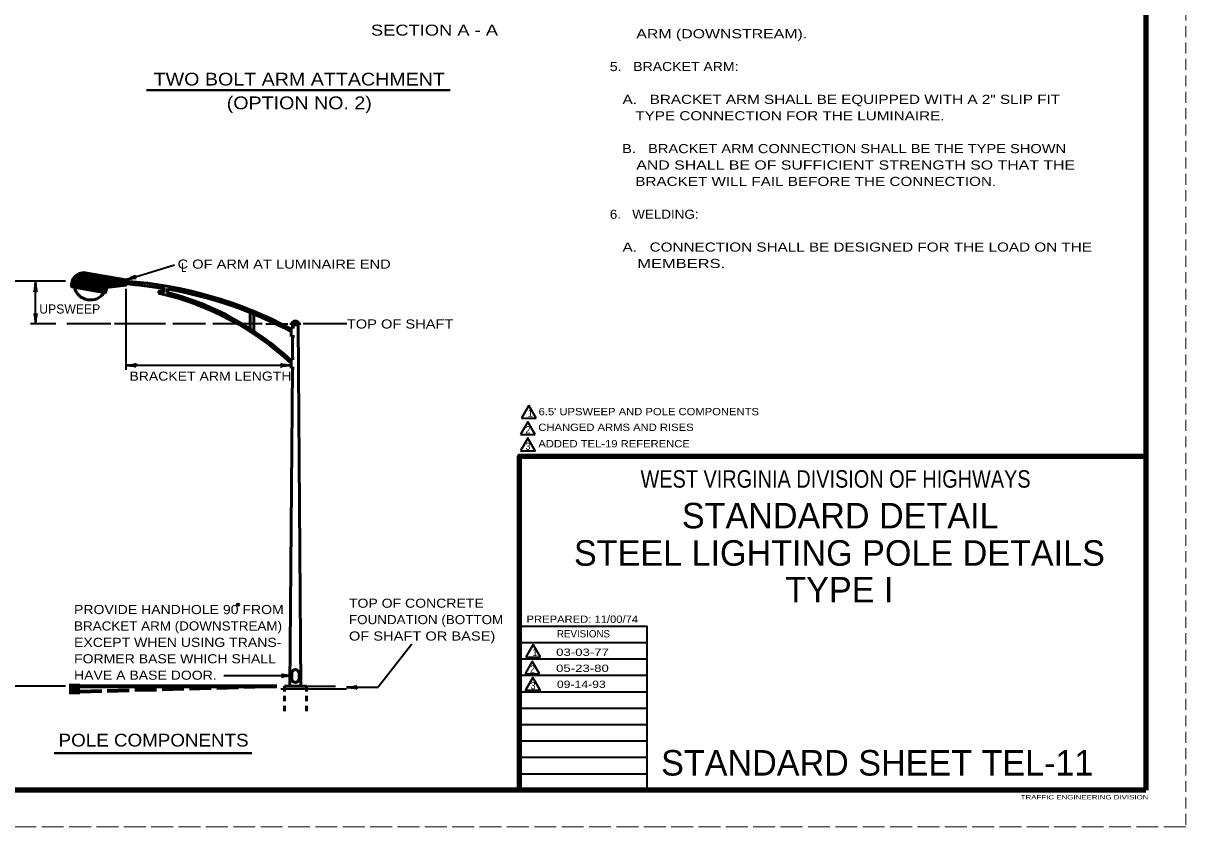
# Model space of a CAD drawing. Extents: x -1 to 679, y 1 to 441.
# Drawn here: x 360.8 to 679.4, y 0.8 to 221.2 of the extents above; entities that cross this region are included whole.
import ezdxf
from ezdxf.enums import TextEntityAlignment as Align

# ---------------------------------------------------------------- set-up
doc = ezdxf.new("R2010")
doc.units = 0
doc.header["$PDMODE"] = 32
doc.header["$PDSIZE"] = 0.5
for name, pattern in [('LONG_DASHED', [7.5, 6, -1.5]), ('MEDIUM_DASHED', [4.5, 3, -1.5]), ('SHORT_DASHED', [2.7, 1.5, -1.2])]:
    doc.linetypes.add(name, pattern=pattern)
doc.layers.add('1', color=7, linetype='Continuous', lineweight=13)
doc.layers.add('61', color=7, linetype='Continuous', lineweight=35)

msp = doc.modelspace()

# ---------------------------------------------------------------- linework, layer by layer
at = {"layer": '1', "linetype": 'MEDIUM_DASHED'}
msp.add_line((679.412, 440.866), (679.392, 0.846), dxfattribs=at)
at = {"layer": '1', "lineweight": 40}
for p, q in [((394.595, 202.791), (477.805, 202.791)), ((369.301, 21.01), (423.451, 21.01))]:
    msp.add_line(p, q, dxfattribs=at)
at = {"layer": '1', "lineweight": 35}
for p, q in [((388.908, 150.796), (402.224, 154.896)), ((372.357, 150.421), (353.908, 150.421)), ((364.189, 138.702), (364.189, 150.421)), ((388.908, 148.296), (388.908, 126.153)), ((369.783, 138.702), (362.783, 138.702)), ((384.783, 138.702), (372.783, 138.702)), ((399.783, 138.702), (385.783, 138.702)), ((410.783, 138.702), (401.783, 138.702)), ((426.283, 138.702), (412.783, 138.702)), ((427.283, 138.702), (433.283, 138.702)), ((449.533, 138.702), (437.533, 138.702)), ((434.213, 127.343), (388.908, 127.343)), ((499.351, 116.373), (497.351, 112.908)), ((501.351, 112.908), (499.351, 116.373)), ((499.081, 111.858), (497.081, 108.394)), ((497.351, 112.908), (501.351, 112.908)), ((501.081, 108.394), (499.081, 111.858)), ((497.081, 108.394), (501.081, 108.394)), ((531.792, 51.266), (496.812, 51.266)), ((467.308, 50.878), (458.129, 39.061)), ((500.599, 50.778), (498.599, 47.314)), ((502.599, 47.314), (500.599, 50.778)), ((531.792, 46.766), (496.812, 46.766)), ((500.329, 46.264), (498.329, 42.8)), ((498.599, 47.314), (502.599, 47.314)), ((502.329, 42.8), (500.329, 46.264)), ((434.485, 42.243), (415.78, 42.243)), ((531.792, 42.266), (496.812, 42.266)), ((498.329, 42.8), (502.329, 42.8)), ((372.357, 39.421), (353.908, 39.421)), ((431.408, 38.671), (449.408, 38.671)), ((438.408, 39.421), (446.408, 39.421)), ((449.404, 39.061), (458.129, 39.061)), ((531.792, 37.746), (496.812, 37.746)), ((531.792, 33.266), (496.812, 33.266)), ((531.792, 28.786), (496.812, 28.786)), ((531.792, 24.286), (496.812, 24.286)), ((531.792, 19.786), (496.812, 19.786)), ((531.792, 15.266), (496.812, 15.266))]:
    msp.add_line(p, q, dxfattribs=at)
at = {"layer": '1', "lineweight": 53}
for p, q in [((374.06, 149.277), (375.11, 150.327)), ((374.061, 149.384), (375.004, 150.327)), ((374.061, 149.172), (375.216, 150.327)), ((374.062, 149.492), (374.898, 150.327)), ((374.069, 149.604), (374.792, 150.327)), ((374.071, 149.075), (375.322, 150.327)), ((374.08, 148.978), (375.428, 150.327)), ((374.083, 149.724), (374.686, 150.327)), ((374.089, 148.882), (375.535, 150.327)), ((374.097, 149.844), (374.639, 150.387)), ((374.118, 149.971), (374.639, 150.493)), ((374.143, 148.83), (375.641, 150.327)), ((374.148, 150.108), (376.717, 152.676)), ((374.179, 150.245), (376.576, 152.642)), ((374.23, 150.402), (376.422, 152.593)), ((374.233, 148.814), (375.747, 150.327)), ((374.284, 150.562), (376.262, 152.54)), ((374.324, 148.798), (375.853, 150.327)), ((374.365, 150.748), (376.076, 152.459)), ((374.414, 148.782), (375.959, 150.327)), ((374.46, 150.949), (375.867, 152.357)), ((374.504, 148.766), (376.065, 150.327)), ((374.594, 148.75), (376.171, 150.327)), ((374.613, 151.209), (375.612, 152.208)), ((374.661, 150.515), (376.85, 152.703)), ((374.684, 148.735), (376.277, 150.327)), ((374.767, 150.515), (376.982, 152.73)), ((374.774, 148.719), (376.383, 150.327)), ((374.865, 148.703), (376.489, 150.327)), ((374.873, 150.515), (377.1, 152.741)), ((374.955, 148.687), (376.595, 150.327)), ((374.98, 150.515), (377.217, 152.752)), ((375.045, 148.671), (376.701, 150.327)), ((375.085, 151.787), (375.088, 151.79)), ((375.086, 150.515), (377.334, 152.763)), ((375.135, 148.655), (376.807, 150.327)), ((375.192, 150.515), (377.44, 152.763)), ((375.225, 148.639), (376.913, 150.327)), ((375.298, 150.515), (377.545, 152.762)), ((375.315, 148.623), (377.019, 150.327)), ((375.404, 150.515), (377.65, 152.761)), ((375.406, 148.607), (377.125, 150.327)), ((375.496, 148.591), (377.232, 150.327)), ((375.51, 150.515), (377.751, 152.756)), ((375.586, 148.576), (377.338, 150.327)), ((375.616, 150.515), (377.847, 152.746)), ((375.676, 148.56), (377.444, 150.327)), ((375.722, 150.515), (377.938, 152.73)), ((375.766, 148.544), (377.55, 150.327)), ((375.828, 150.515), (378.028, 152.714)), ((375.856, 148.528), (377.656, 150.327)), ((375.934, 150.515), (378.118, 152.699)), ((375.947, 148.512), (377.762, 150.327)), ((376.037, 148.496), (377.868, 150.327)), ((376.04, 150.515), (378.208, 152.683)), ((376.127, 148.48), (377.974, 150.327)), ((376.146, 150.515), (378.298, 152.667)), ((376.217, 148.464), (378.08, 150.327)), ((376.252, 150.515), (378.388, 152.651)), ((376.307, 148.448), (378.186, 150.327)), ((376.358, 150.515), (378.479, 152.635)), ((376.397, 148.433), (378.292, 150.327)), ((376.464, 150.515), (378.569, 152.619)), ((376.488, 148.417), (378.398, 150.327)), ((376.571, 150.515), (378.659, 152.603)), ((376.578, 148.401), (378.504, 150.327)), ((376.668, 148.385), (378.61, 150.327)), ((376.677, 150.515), (378.749, 152.587)), ((376.758, 148.369), (378.716, 150.327)), ((376.783, 150.515), (378.839, 152.571)), ((376.848, 148.353), (378.823, 150.327)), ((376.889, 150.515), (378.929, 152.555)), ((376.938, 148.337), (378.929, 150.327)), ((376.995, 150.515), (379.02, 152.54)), ((377.029, 148.321), (379.035, 150.327)), ((377.101, 150.515), (379.11, 152.524)), ((377.119, 148.305), (379.141, 150.327)), ((377.207, 150.515), (379.2, 152.508)), ((377.209, 148.289), (379.247, 150.327)), ((377.299, 148.273), (379.353, 150.327)), ((377.313, 150.515), (379.29, 152.492)), ((377.389, 148.258), (379.459, 150.327)), ((377.419, 150.515), (379.38, 152.476)), ((377.479, 148.242), (379.565, 150.327)), ((377.525, 150.515), (379.471, 152.46)), ((377.57, 148.226), (379.671, 150.327)), ((377.631, 150.515), (379.561, 152.444)), ((377.66, 148.21), (379.777, 150.327)), ((377.737, 150.515), (379.651, 152.428)), ((377.75, 148.194), (379.883, 150.327)), ((377.84, 148.178), (379.989, 150.327)), ((377.843, 150.515), (379.741, 152.412)), ((377.93, 148.162), (380.095, 150.327)), ((377.949, 150.515), (379.831, 152.397)), ((378.02, 148.146), (380.201, 150.327)), ((378.055, 150.515), (379.921, 152.381)), ((378.111, 148.13), (380.308, 150.327)), ((378.162, 150.515), (380.012, 152.365)), ((378.201, 148.114), (380.414, 150.327)), ((378.268, 150.515), (380.102, 152.349)), ((378.291, 148.099), (380.52, 150.327)), ((378.374, 150.515), (380.192, 152.333)), ((378.381, 148.083), (380.626, 150.327)), ((378.471, 148.067), (380.732, 150.327)), ((378.48, 150.515), (380.282, 152.317)), ((378.561, 148.051), (380.838, 150.327)), ((378.586, 150.515), (380.372, 152.301)), ((378.652, 148.035), (380.944, 150.327)), ((378.692, 150.515), (380.462, 152.285)), ((378.742, 148.019), (381.05, 150.327)), ((378.798, 150.515), (380.553, 152.269)), ((378.832, 148.003), (381.156, 150.327)), ((378.904, 150.515), (380.643, 152.253)), ((378.922, 147.987), (381.262, 150.327)), ((379.01, 150.515), (380.733, 152.237)), ((379.012, 147.971), (381.368, 150.327)), ((379.102, 147.955), (381.474, 150.327)), ((379.116, 150.515), (380.823, 152.222)), ((379.193, 147.94), (381.58, 150.327)), ((379.222, 150.515), (380.913, 152.206)), ((379.283, 147.924), (381.686, 150.327)), ((379.328, 150.515), (381.003, 152.19)), ((379.373, 147.908), (381.792, 150.327)), ((379.434, 150.515), (381.094, 152.174)), ((379.463, 147.892), (381.899, 150.327)), ((379.54, 150.515), (381.184, 152.158)), ((379.553, 147.876), (382.005, 150.327)), ((379.643, 147.86), (382.111, 150.327)), ((379.647, 150.515), (381.274, 152.142)), ((379.734, 147.844), (382.217, 150.327)), ((379.753, 150.515), (381.364, 152.126)), ((379.824, 147.828), (382.323, 150.327)), ((379.859, 150.515), (381.454, 152.11)), ((379.914, 147.812), (382.429, 150.327)), ((379.965, 150.515), (381.544, 152.094)), ((380.004, 147.796), (382.535, 150.327)), ((380.071, 150.515), (381.635, 152.078)), ((380.094, 147.781), (382.641, 150.327)), ((380.177, 150.515), (381.725, 152.063)), ((380.184, 147.765), (382.747, 150.327)), ((380.275, 147.749), (382.853, 150.327)), ((380.283, 150.515), (381.815, 152.047)), ((380.365, 147.733), (382.959, 150.327)), ((380.389, 150.515), (381.905, 152.031)), ((380.455, 147.717), (383.065, 150.327)), ((380.495, 150.515), (381.995, 152.015)), ((380.545, 147.701), (383.171, 150.327)), ((380.601, 150.515), (382.085, 151.999)), ((380.635, 147.685), (383.277, 150.327)), ((380.707, 150.515), (382.175, 151.983)), ((380.725, 147.669), (383.383, 150.327)), ((380.813, 150.515), (382.266, 151.967)), ((380.816, 147.653), (383.489, 150.327)), ((380.906, 147.637), (383.596, 150.327)), ((380.919, 150.515), (382.356, 151.951)), ((380.996, 147.622), (383.702, 150.327)), ((381.025, 150.515), (382.446, 151.935)), ((381.086, 147.606), (383.808, 150.327)), ((381.131, 150.515), (382.536, 151.919)), ((381.176, 147.59), (383.914, 150.327)), ((381.237, 150.515), (382.626, 151.904)), ((381.266, 147.574), (384.02, 150.327)), ((381.344, 150.515), (382.716, 151.888)), ((381.357, 147.558), (384.126, 150.327)), ((381.447, 147.542), (384.232, 150.327)), ((381.45, 150.515), (382.807, 151.872)), ((381.537, 147.526), (384.338, 150.327)), ((381.556, 150.515), (382.897, 151.856)), ((381.627, 147.51), (384.444, 150.327)), ((381.662, 150.515), (382.987, 151.84)), ((381.717, 147.494), (384.55, 150.327)), ((381.768, 150.515), (383.077, 151.824)), ((381.807, 147.478), (384.656, 150.327)), ((381.874, 150.515), (383.167, 151.808)), ((381.898, 147.463), (384.762, 150.327)), ((381.98, 150.515), (383.257, 151.792)), ((381.988, 147.447), (384.868, 150.327)), ((382.078, 147.431), (384.974, 150.327)), ((382.086, 150.515), (383.348, 151.776)), ((382.168, 147.415), (385.08, 150.327)), ((382.192, 150.515), (383.438, 151.761)), ((382.258, 147.399), (385.187, 150.327)), ((382.298, 150.515), (383.528, 151.745)), ((382.348, 147.383), (385.293, 150.327)), ((382.404, 150.515), (383.618, 151.729)), ((382.51, 150.515), (383.708, 151.713)), ((382.616, 150.515), (383.798, 151.697)), ((382.722, 150.515), (383.889, 151.681)), ((382.828, 150.515), (383.979, 151.665)), ((382.935, 150.515), (384.069, 151.649)), ((383.041, 150.515), (384.159, 151.633)), ((383.147, 150.515), (384.249, 151.617)), ((383.253, 150.515), (384.339, 151.601)), ((383.359, 150.515), (384.43, 151.586)), ((383.465, 150.515), (384.52, 151.57)), ((383.571, 150.515), (384.61, 151.554)), ((383.677, 150.515), (384.7, 151.538)), ((383.732, 148.66), (385.399, 150.327)), ((383.783, 150.515), (384.79, 151.522)), ((383.853, 148.675), (385.505, 150.327)), ((383.889, 150.515), (384.88, 151.506)), ((383.974, 148.69), (385.611, 150.327)), ((383.995, 150.515), (384.971, 151.49)), ((384.095, 148.705), (385.717, 150.327)), ((384.101, 150.515), (385.061, 151.474)), ((384.207, 150.515), (385.151, 151.458)), ((384.216, 148.72), (385.823, 150.327)), ((384.313, 150.515), (385.241, 151.442)), ((384.337, 148.735), (385.929, 150.327)), ((384.419, 150.515), (385.331, 151.427)), ((384.457, 148.75), (386.035, 150.327)), ((384.525, 150.515), (385.421, 151.411)), ((384.578, 148.764), (386.141, 150.327)), ((384.632, 150.515), (385.512, 151.395)), ((384.699, 148.779), (386.247, 150.327)), ((384.738, 150.515), (385.602, 151.379)), ((384.82, 148.794), (386.353, 150.327)), ((384.844, 150.515), (385.692, 151.363)), ((384.941, 148.809), (386.459, 150.327)), ((384.95, 150.515), (385.782, 151.347)), ((385.056, 150.515), (385.872, 151.331)), ((385.062, 148.824), (386.565, 150.327)), ((385.162, 150.515), (385.962, 151.315)), ((385.183, 148.839), (386.671, 150.327)), ((385.268, 150.515), (386.053, 151.299)), ((385.304, 148.853), (386.778, 150.327)), ((385.374, 150.515), (386.143, 151.284)), ((385.425, 148.868), (386.884, 150.327)), ((385.48, 150.515), (386.233, 151.268)), ((385.546, 148.883), (386.99, 150.327)), ((385.586, 150.515), (386.323, 151.252)), ((385.666, 148.898), (387.096, 150.327)), ((385.692, 150.515), (386.413, 151.236)), ((385.787, 148.913), (387.202, 150.327)), ((385.798, 150.515), (386.503, 151.22)), ((385.904, 150.515), (386.594, 151.204)), ((385.908, 148.928), (387.308, 150.327)), ((386.01, 150.515), (386.684, 151.188)), ((386.029, 148.943), (387.414, 150.327)), ((386.116, 150.515), (386.774, 151.172)), ((386.15, 148.957), (387.52, 150.327)), ((386.223, 150.515), (386.864, 151.156)), ((386.271, 148.972), (387.626, 150.327)), ((386.329, 150.515), (386.954, 151.14)), ((386.392, 148.987), (387.732, 150.327)), ((386.435, 150.515), (387.044, 151.125)), ((386.513, 149.002), (387.838, 150.327)), ((386.541, 150.515), (387.135, 151.109)), ((386.634, 149.017), (387.944, 150.327)), ((386.647, 150.515), (387.225, 151.093)), ((386.753, 150.515), (387.315, 151.077)), ((386.755, 149.032), (388.05, 150.327)), ((386.859, 150.515), (387.405, 151.061)), ((386.876, 149.047), (388.156, 150.327)), ((386.965, 150.515), (387.495, 151.045)), ((386.997, 149.061), (388.262, 150.327)), ((387.071, 150.515), (387.585, 151.029)), ((387.117, 149.076), (388.368, 150.327)), ((387.177, 150.515), (387.676, 151.013)), ((387.238, 149.091), (388.475, 150.327)), ((387.283, 150.515), (387.766, 150.997)), ((387.359, 149.106), (388.908, 150.654)), ((387.389, 150.515), (387.856, 150.981)), ((387.48, 149.121), (388.908, 150.548)), ((387.495, 150.515), (387.946, 150.966)), ((387.601, 150.515), (388.036, 150.95)), ((387.601, 149.136), (388.908, 150.442)), ((387.707, 150.515), (388.126, 150.934)), ((387.722, 149.15), (388.908, 150.336)), ((387.814, 150.515), (388.217, 150.918)), ((387.843, 149.165), (388.908, 150.23)), ((387.92, 150.515), (388.307, 150.902)), ((387.964, 149.18), (388.908, 150.124)), ((388.026, 150.515), (388.397, 150.886)), ((388.085, 149.195), (388.908, 150.018)), ((388.132, 150.515), (388.487, 150.87)), ((388.206, 149.21), (388.908, 149.912)), ((388.238, 150.515), (388.577, 150.854)), ((388.327, 149.225), (388.908, 149.806)), ((388.344, 150.515), (388.667, 150.838)), ((388.45, 150.515), (388.758, 150.822)), ((388.533, 150.492), (388.848, 150.807)), ((388.533, 150.385), (388.908, 150.76)), ((383.362, 147.204), (374.093, 148.839)), ((382.439, 147.367), (383.688, 148.616)), ((382.529, 147.351), (383.656, 148.478)), ((382.619, 147.335), (383.624, 148.34)), ((382.709, 147.319), (383.592, 148.202)), ((382.799, 147.304), (383.56, 148.065)), ((382.889, 147.288), (383.528, 147.927)), ((382.98, 147.272), (383.497, 147.789)), ((383.07, 147.256), (383.465, 147.651)), ((383.16, 147.24), (383.433, 147.513)), ((383.25, 147.224), (383.401, 147.375)), ((383.34, 147.208), (383.369, 147.237)), ((388.447, 149.239), (388.908, 149.7)), ((388.568, 149.254), (388.908, 149.594)), ((388.689, 149.269), (388.908, 149.488)), ((388.81, 149.284), (388.908, 149.382)), ((399.408, 147.342), (399.408, 148.609)), ((400.345, 147.107), (400.345, 148.449)), ((423.033, 137.388), (423.033, 141.794)), ((423.97, 136.776), (423.97, 141.413)), ((435.154, 137.858), (434.279, 137.858)), ((434.279, 137.858), (434.279, 135.233)), ((434.283, 138.983), (436.533, 138.983)), ((434.283, 138.983), (434.283, 138.421)), ((434.283, 138.421), (436.533, 138.421)), ((434.658, 138.421), (434.654, 137.858)), ((436.908, 39.421), (436.158, 138.421)), ((436.533, 138.983), (436.533, 138.421)), ((435.154, 135.233), (434.279, 135.233)), ((434.634, 135.233), (434.588, 129.233)), ((435.088, 129.233), (434.213, 129.233)), ((434.213, 129.233), (434.213, 126.608)), ((434.568, 126.608), (433.908, 39.421)), ((435.088, 126.608), (434.213, 126.608)), ((434.423, 41.417), (434.423, 42.917)), ((436.393, 41.417), (436.393, 42.917)), ((432.408, 39.421), (438.408, 39.421))]:
    msp.add_line(p, q, dxfattribs=at)
at = {"layer": '1', "lineweight": 106}
for p, q in [((373.357, 39.421), (376.357, 39.421)), ((373.357, 37.921), (376.357, 37.921))]:
    msp.add_line(p, q, dxfattribs=at)
at = {"layer": '1', "lineweight": 70}
msp.add_line((376.357, 39.421), (430.357, 39.421), dxfattribs=at)
at = {"layer": '1', "linetype": 'LONG_DASHED', "lineweight": 70}
msp.add_line((376.357, 37.921), (430.357, 39.421), dxfattribs=at)
at = {"layer": '1', "linetype": 'SHORT_DASHED', "lineweight": 53}
for p, q in [((432.408, 39.421), (432.408, 31.421)), ((438.408, 39.421), (438.408, 31.421))]:
    msp.add_line(p, q, dxfattribs=at)
at = {"layer": '1', "lineweight": 53}
msp.add_lwpolyline([(374.639, 150.515), (388.533, 150.515), (388.533, 150.327), (374.639, 150.327)], close=True, dxfattribs=at)
msp.add_lwpolyline([(377.829, 152.75), (388.908, 150.796), (388.908, 149.296), (383.697, 148.656), (383.362, 147.204)], dxfattribs=at)
at = {"layer": '1', "lineweight": 35}
for points in [[(497.081, 103.898), (501.081, 103.898), (499.081, 107.362)], [(500.487, 41.747), (498.487, 38.282), (502.487, 38.282)]]:
    msp.add_lwpolyline(points, close=True, dxfattribs=at)
at = {"layer": '1', "lineweight": 158}
msp.add_lwpolyline([(496.792, 10.826), (496.792, 102.406), (668.452, 102.406)], dxfattribs=at)
at = {"layer": '1', "lineweight": 35}
msp.add_lwpolyline([(531.792, 10.786), (531.792, 55.746), (496.812, 55.746)], dxfattribs=at)
msp.add_circle((419.688, 61.76), 0.322, dxfattribs=at)
at = {"layer": '1', "lineweight": 53}
for centre, radius, start, end in [((377.485, 149.339), 3.428, 84.23953, 188.38162), ((380.776, 37.331), 113.382, 61.84402, 85.88743), ((379.232, 149.801), 4.534, 193.94762, 326.05059), ((380.776, 36.581), 113.382, 80.54208, 85.88743), ((398.345, 147.421), 0.38, 99.37484, 260.62516), ((398.457, 147.668), 0.646, 235.53017, 254.38288), ((380.895, 71.816), 77.945, 76.2603, 77.11012), ((380.895, 71.066), 77.945, 46.83897, 77.11012), ((380.776, 36.581), 113.382, 61.84402, 80.06146), ((380.895, 71.816), 77.945, 46.83897, 75.54976), ((435.408, 138.706), 0.796, 20.3922, 159.6078), ((435.408, 42.941), 0.985, 358.58875, 181.41125), ((435.408, 41.381), 0.985, 178.58875, 1.41125)]:
    msp.add_arc(centre, radius, start, end, dxfattribs=at)
at = {"layer": '1', "lineweight": 40}
for centre, major_axis, ratio, start_param, end_param in [((363.978, 149.3), (0.176, 1.756), 0.07063, 3.1407148, 5.41811), ((364.466, 149.33), (-0.156, 1.786), 0.122415, 0.8963533, 3.1415927), ((389.869, 151.381), (-1.661, -0.675), 0.122415, 0.8963533, 3.1415927), ((390.041, 150.923), (1.73, 0.349), 0.07063, 6.2823074, 8.5597026), ((363.913, 139.793), (0.156, -1.786), 0.122415, 0.8963533, 3.1415927), ((364.401, 139.823), (-0.176, -1.756), 0.07063, 3.1407148, 5.41811), ((389.999, 127.619), (-1.786, -0.156), 0.122415, 0.8963533, 3.1415927), ((389.999, 127.619), (-1.786, -0.156), 0.122415, 0.8963533, 3.1415927), ((433.093, 127.554), (1.756, -0.176), 0.07063, 3.1407148, 5.41811), ((433.093, 127.554), (1.756, -0.176), 0.07063, 3.1407148, 5.41811), ((390.028, 127.131), (-1.756, 0.176), 0.07063, 3.1407148, 5.41811), ((390.028, 127.131), (-1.756, 0.176), 0.07063, 3.1407148, 5.41811), ((433.122, 127.067), (1.786, 0.156), 0.122415, 0.8963533, 3.1415927), ((433.122, 127.067), (1.786, 0.156), 0.122415, 0.8963533, 3.1415927), ((433.394, 41.966), (1.786, 0.156), 0.122415, 0.8963533, 3.1415927), ((433.365, 42.454), (1.756, -0.176), 0.07063, 3.1407148, 5.41811), ((450.524, 38.849), (-1.756, 0.176), 0.07063, 3.1407148, 5.41811), ((450.495, 39.337), (-1.786, -0.156), 0.122415, 0.8963533, 3.1415927)]:
    msp.add_ellipse(centre, major_axis=major_axis, ratio=ratio, start_param=start_param, end_param=end_param, dxfattribs=at)
at = {"layer": '1'}
msp.add_point((374.093, 148.839), dxfattribs=at)
at = {"layer": '61', "lineweight": 158}
for p, q in [((668.432, 430.866), (668.452, 10.826)), ((668.452, 10.826), (29.392, 10.846))]:
    msp.add_line(p, q, dxfattribs=at)
at = {"layer": '61', "linetype": 'LONG_DASHED', "lineweight": 13}
msp.add_line((679.392, 0.846), (-0.668, 0.826), dxfattribs=at)

# ---------------------------------------------------------------- texts
at = {"layer": '1'}
for s, height, width, p in [('SECTION A - A', 3, 1.25, (456.105, 217.767)), ('      ARM (DOWNSTREAM).', 2.5, 1.3, (521.582, 217.031)), ('5.   BRACKET ARM:', 2.5, 1.15, (521.582, 208.031)), ('   A.   BRACKET ARM SHALL BE EQUIPPED WITH A 2" SLIP FIT', 2.5, 1.25, (521.582, 199.031)), ('      TYPE CONNECTION FOR THE LUMINAIRE.', 2.5, 1.25, (521.582, 194.531)), ('   B.   BRACKET ARM CONNECTION SHALL BE THE TYPE SHOWN', 2.5, 1.2, (521.582, 185.531)), ('      AND SHALL BE OF SUFFICIENT STRENGTH SO THAT THE', 2.5, 1.3, (521.582, 181.031)), ('      BRACKET WILL FAIL BEFORE THE CONNECTION.', 2.5, 1.25, (521.582, 176.531)), ('6.   WELDING:', 2.5, 1.1, (521.582, 167.531)), ('   A.   CONNECTION SHALL BE DESIGNED FOR THE LOAD ON THE', 2.5, 1.25, (521.582, 158.531)), ('C OF ARM AT LUMINAIRE END', 2.5, 1.2, (403.116, 153.86)), ('      MEMBERS. ', 2.5, 1.35, (521.582, 154.031)), ('L', 2.5, 0.75, (404.119, 152.948)), ('TOP OF SHAFT', 2.5, 1.2, (449.507, 137.449)), ('BRACKET ARM LENGTH', 2.5, 1.15, (389.901, 123.135)), ("6.5' UPSWEEP AND POLE COMPONENTS", 2, 1.15, (502.038, 113.669)), ('2', 2, 0.9, (498.461, 108.665)), ('CHANGED ARMS AND RISES', 2, 1.15, (501.977, 109.358)), ('3', 2, 0.9, (498.461, 104.169)), ('ADDED TEL-19 REFERENCE', 2, 1.15, (501.977, 104.862)), ('PROVIDE HANDHOLE 90 FROM', 2.5, 1.15, (374.735, 59.136)), ('TOP OF CONCRETE', 2.5, 1.15, (450.072, 60.879)), ('FOUNDATION (BOTTOM', 2.5, 1.1, (450.072, 56.379)), ('PREPARED: 11/00/74', 1.998, 1.15, (498.752, 56.746)), ('BRACKET ARM (DOWNSTREAM)', 2.5, 1.1, (374.735, 54.636)), ('OF SHAFT OR BASE)', 2.5, 1.2, (450.072, 51.879)), ('EXCEPT WHEN USING TRANS-', 2.5, 1.15, (374.735, 50.136)), ('FORMER BASE WHICH SHALL', 2.5, 1.15, (374.735, 45.636)), ('2', 2, 0.9, (499.709, 43.07)), ('HAVE A BASE DOOR.', 2.5, 1.15, (374.735, 41.136)), ('3', 2, 0.9, (499.867, 38.553)), ('POLE COMPONENTS', 3.5, 1.1, (370.51, 22.825)), ('TRAFFIC ENGINEERING DIVISION', 1.2, 1.35, (634.172, 8.326))]:
    msp.add_text(s, height=height, dxfattribs=dict(at, width=width)).set_placement(p)
for s, height, width, p in [('TWO BOLT ARM ATTACHMENT', 3.5, 1.15, (436.466, 204.074)), ('(OPTION NO. 2)', 3.5, 1.15, (436.466, 197.574)), ('WEST VIRGINIA DIVISION OF HIGHWAYS', 4.795, 0.85, (583.44, 93.806)), ('03-03-77', 2, 1.35, (514.092, 47.686)), ('05-23-80', 2, 1.35, (514.072, 43.286)), ('09-14-93', 2, 1.25, (513.761, 38.886))]:
    msp.add_text(s, height=height, dxfattribs=dict(at, width=width)).set_placement(p, align=Align.CENTER)
for s, height, p in [('UPSWEEP', 2.5, (365.202, 141.552)), ('1', 2, (499.067, 113.246)), ('REVISIONS', 1.998, (507.072, 52.746)), ('1', 2, (500.315, 47.652)), ('STANDARD SHEET TEL-11', 6.993, (535.632, 14.866))]:
    msp.add_text(s, height=height, dxfattribs=at).set_placement(p)
for s, p in [('STANDARD DETAIL', (584.709, 82.646)), ('STEEL LIGHTING POLE DETAILS', (584.497, 72.4)), ('TYPE I', (584.497, 62.32))]:
    msp.add_text(s, height=6.993, dxfattribs=at).set_placement(p, align=Align.CENTER)

doc.saveas('drawing.dxf')
